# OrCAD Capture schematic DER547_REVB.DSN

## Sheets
1 PAGE2: size C
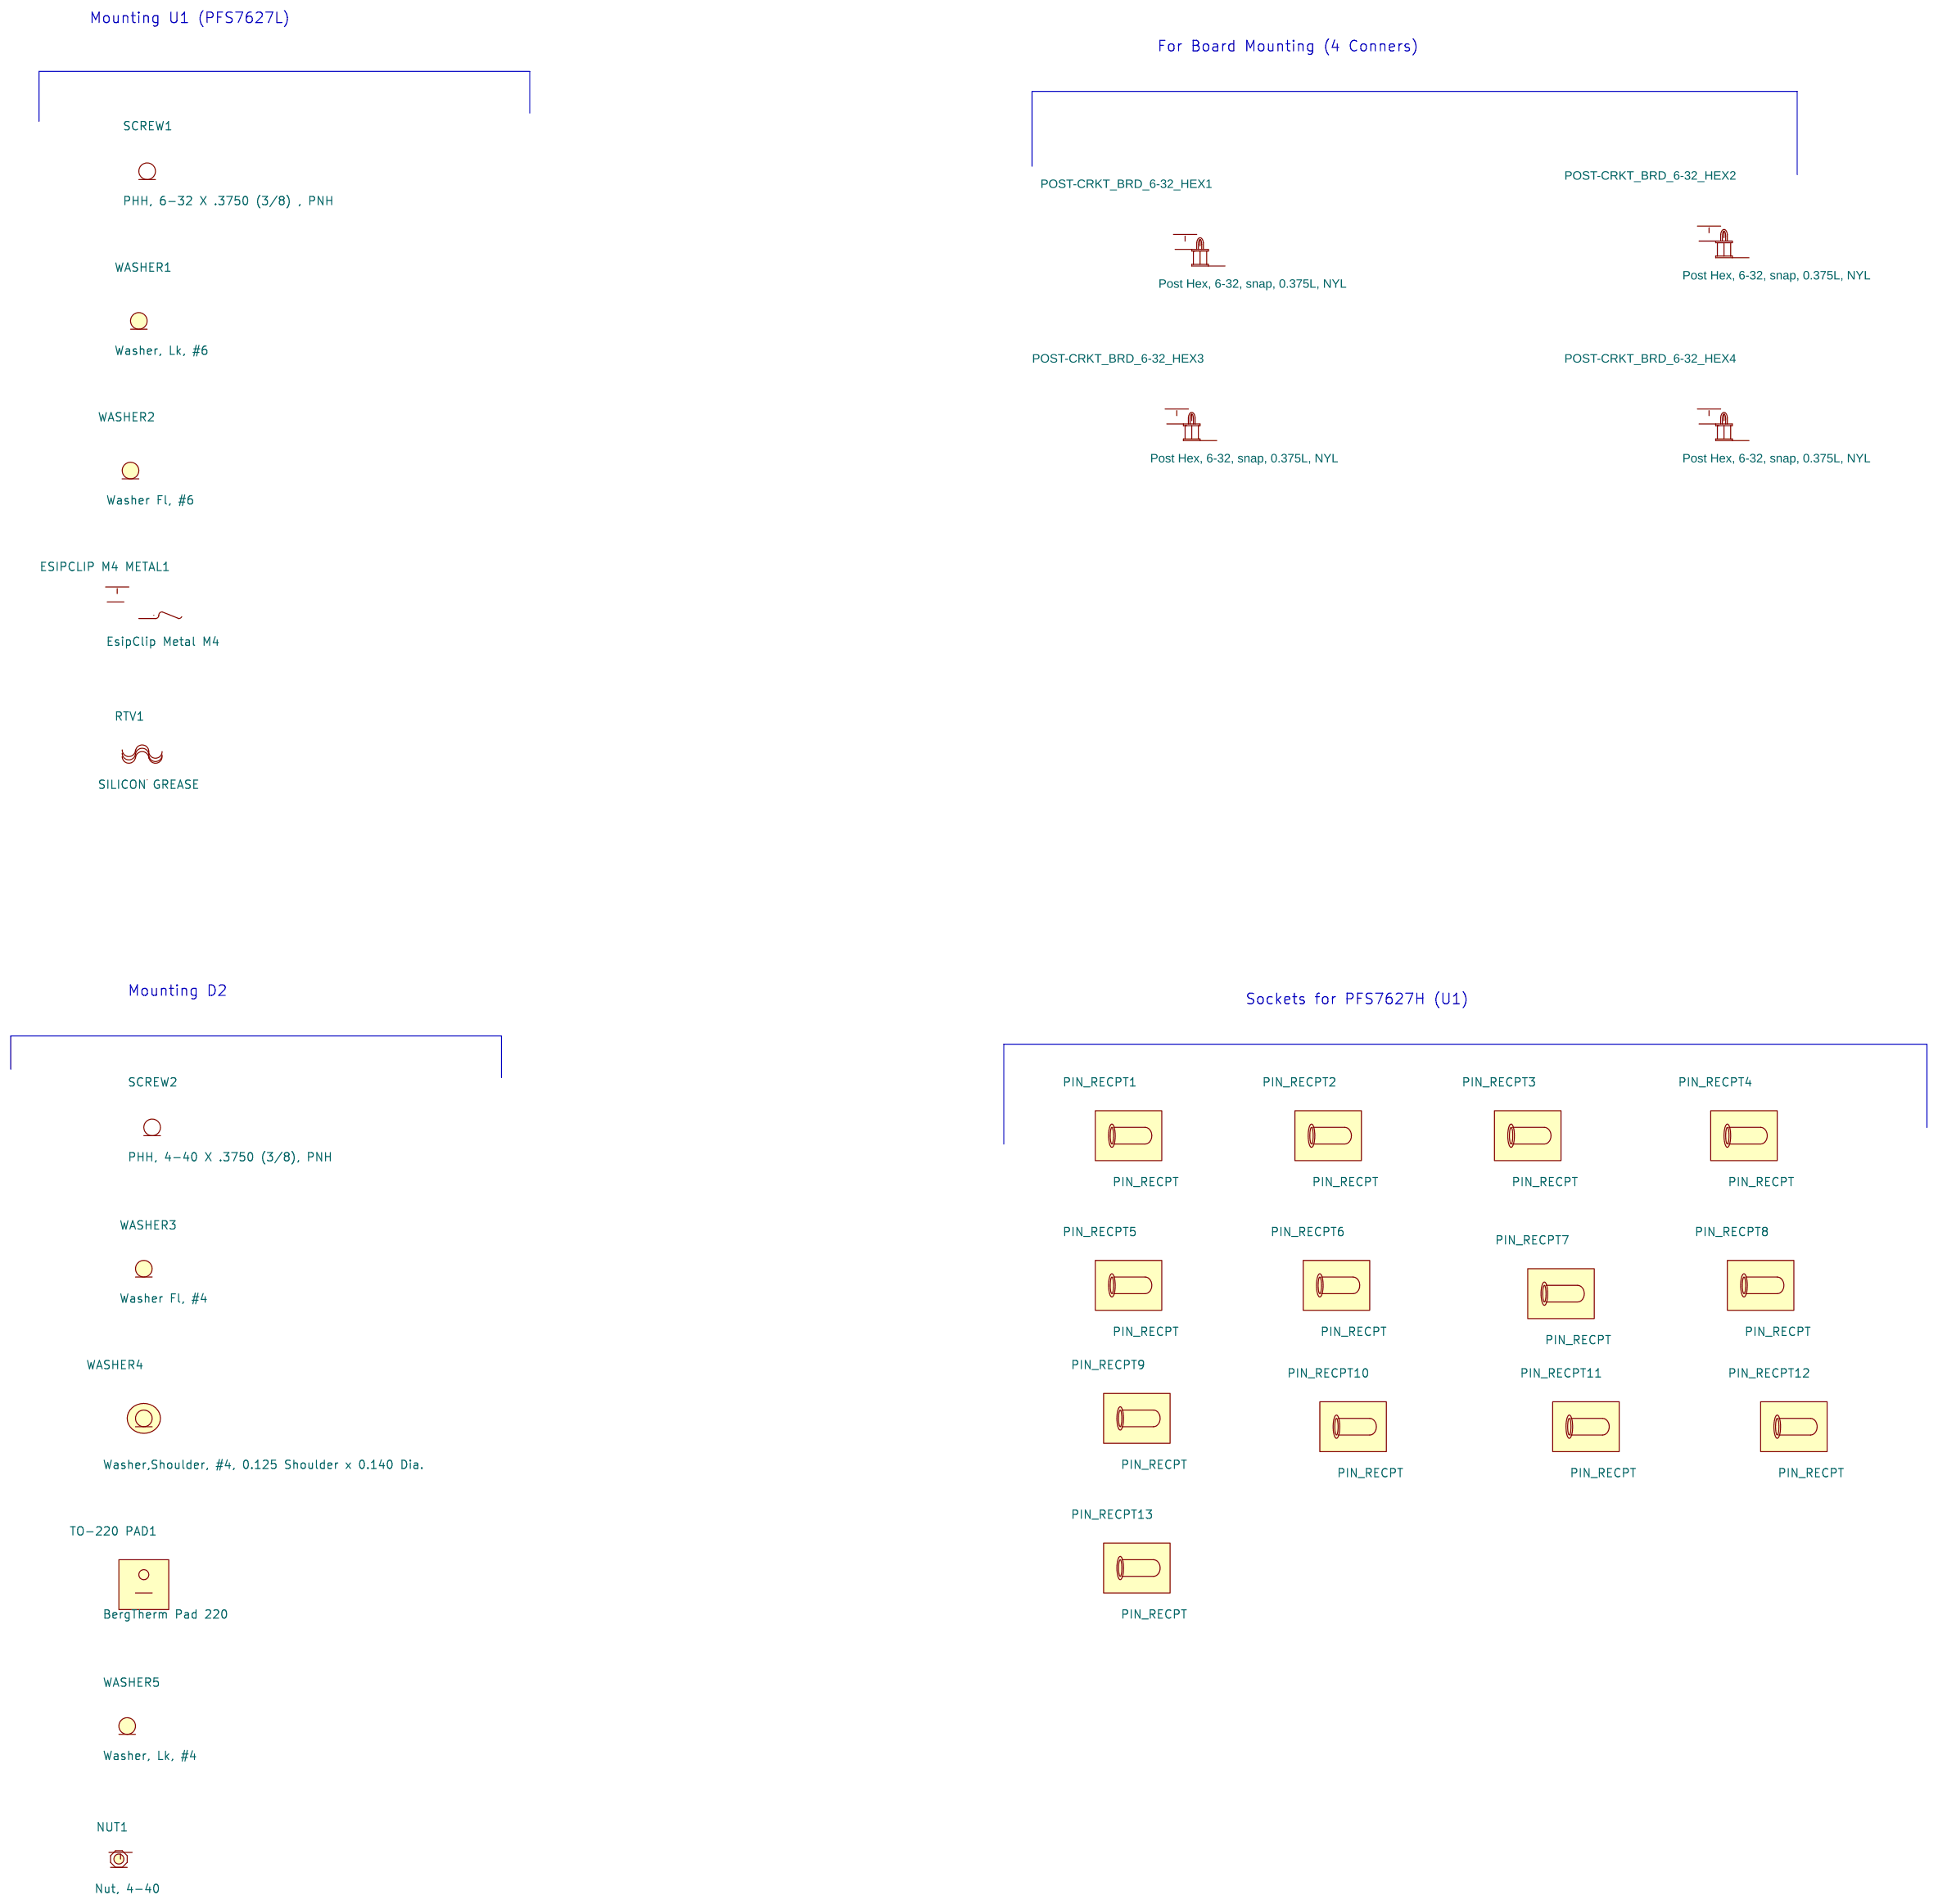
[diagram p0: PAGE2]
2 PAGE1: size C; title: DER547; rev: A
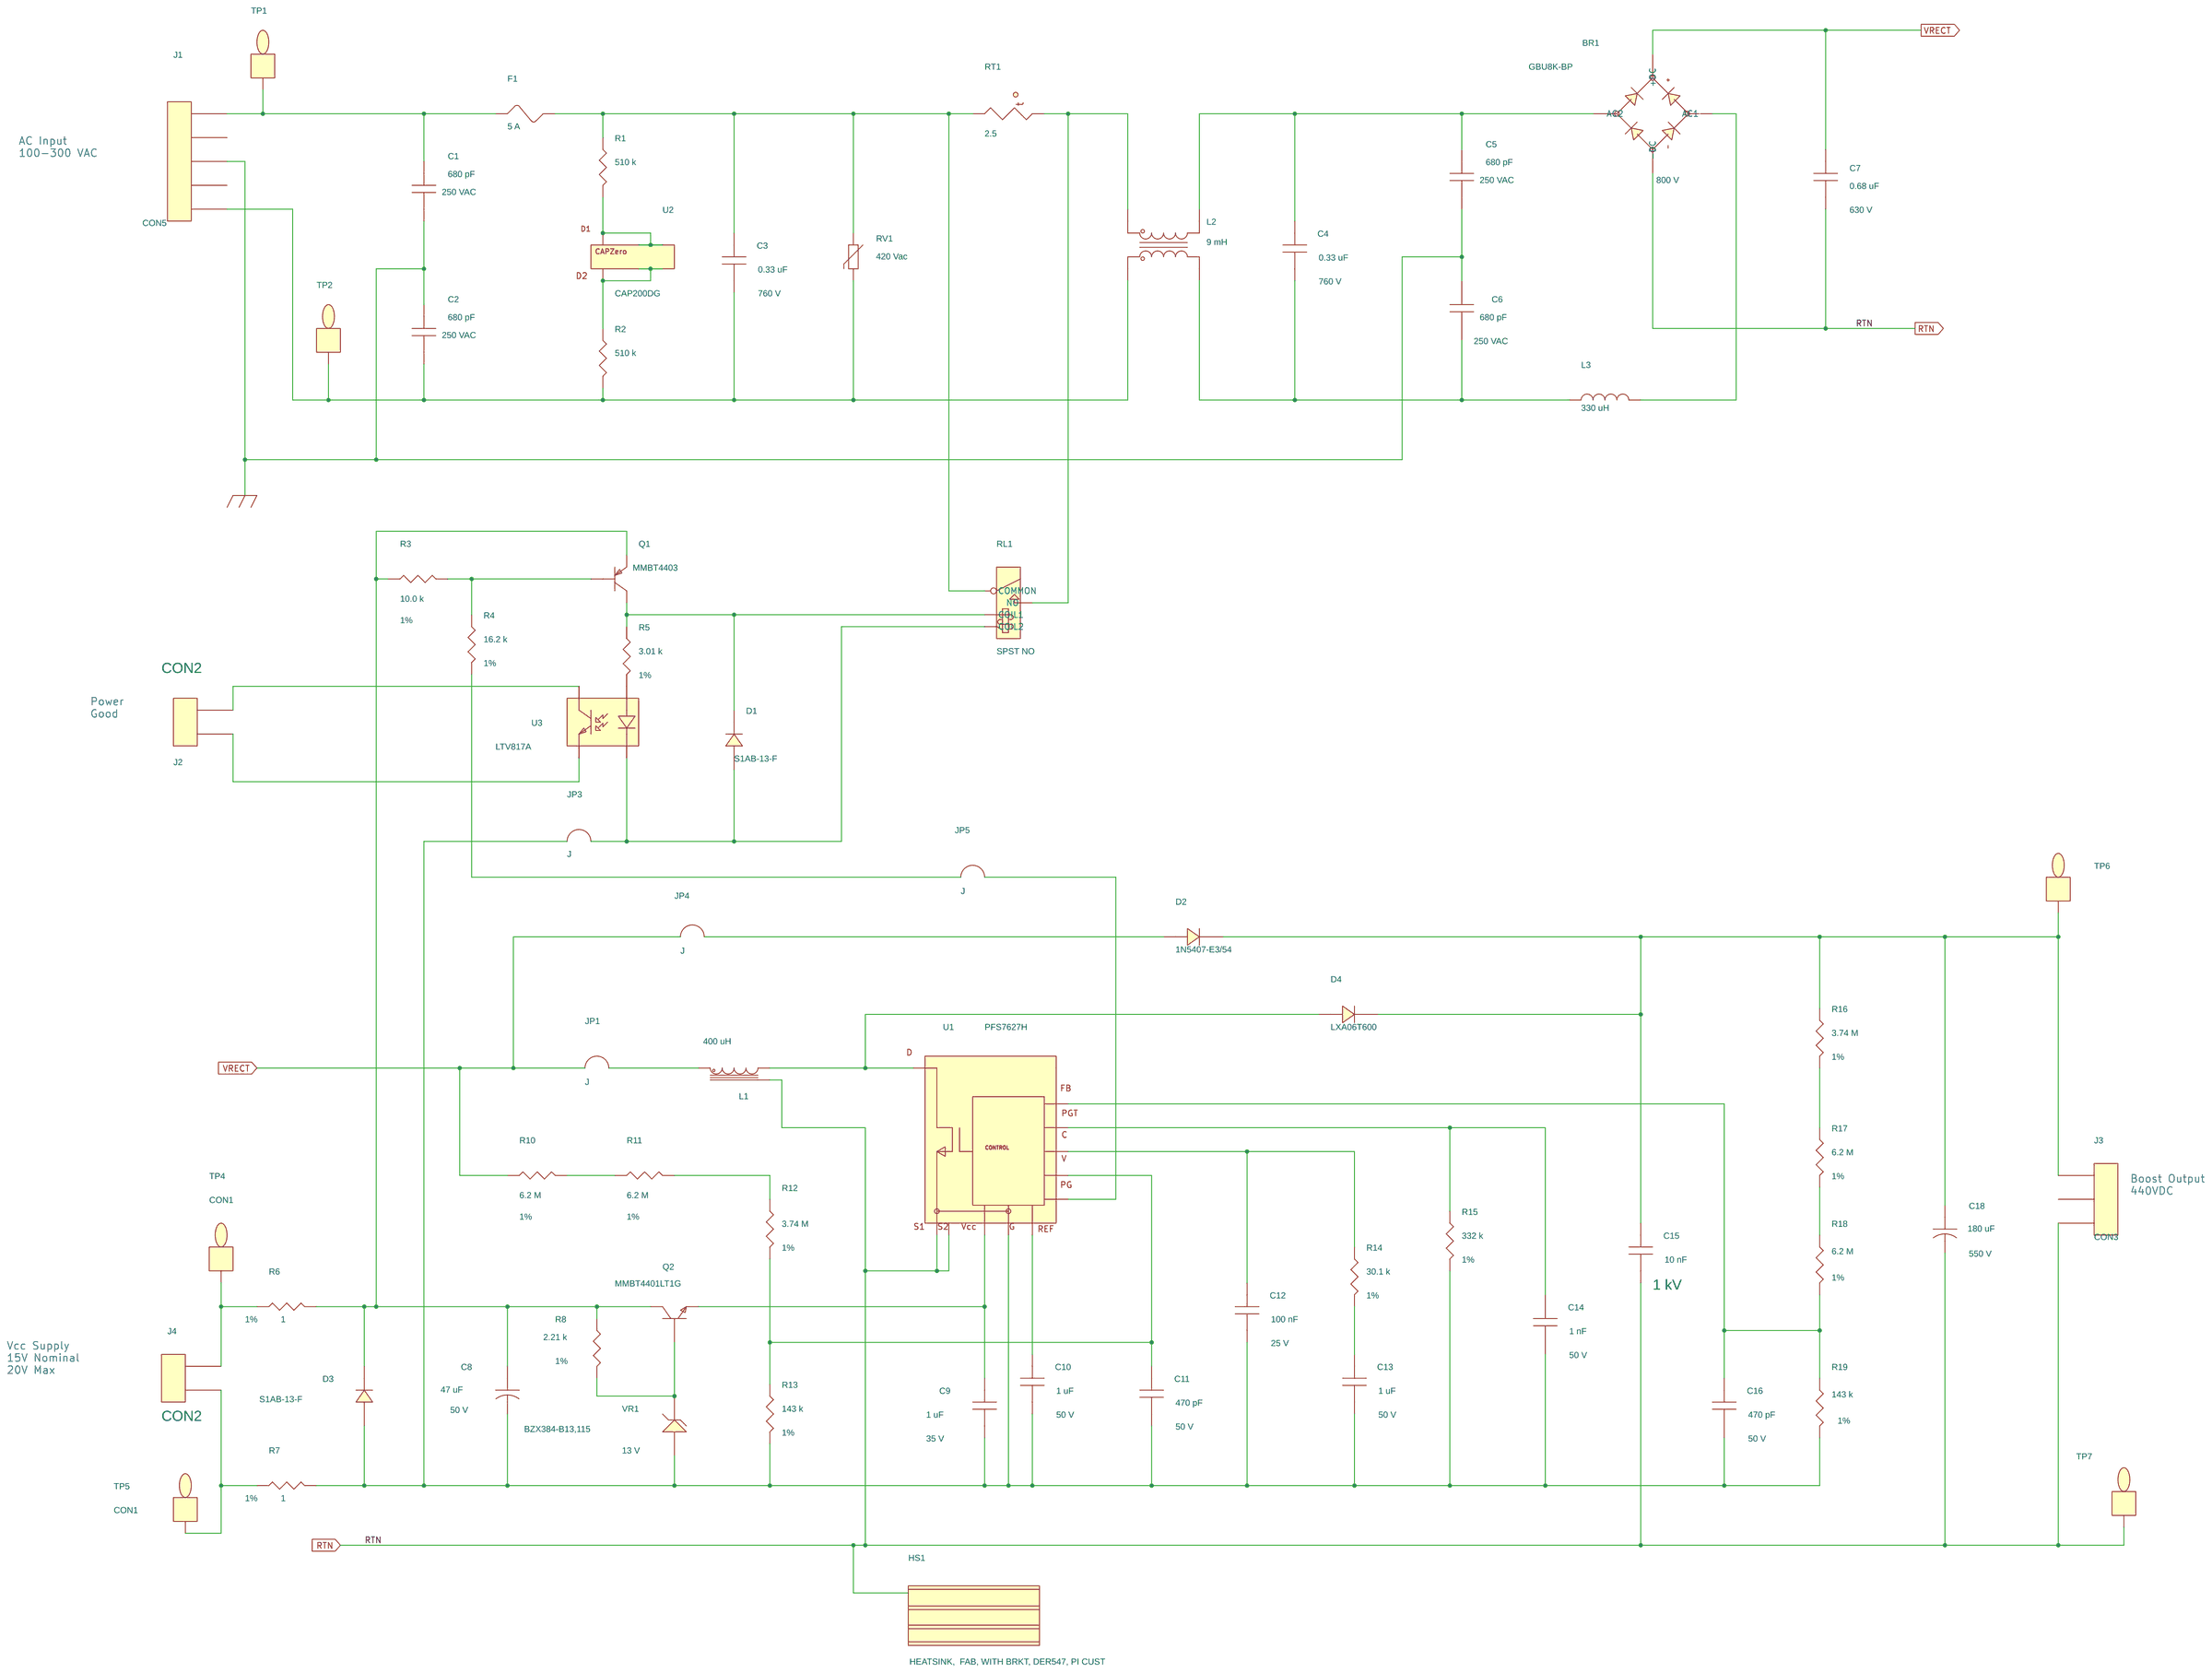
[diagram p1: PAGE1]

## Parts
sheet PAGE1
BR1  GBU8K-BP  [pidaxbridgegbu8]
C1  680 pF  [pinpycaprad470x210ls380040]
C2  680 pF  [pinpycaprad470x210ls380040]
C3  0.33 uF  [pi_np_caprad709x354ls590d050]
C4  0.33 uF  [pi_np_caprad709x354ls590d050]
C5  680 pF  [pinpycaprad470x210ls380040]
C6  680 pF  [pinpycaprad470x210ls380040]
C7  0.68 uF  [pi_np_caprad717x472ls590d050]
C8  47 uF  [pipolcapcyld250ls100030]
C9  1 uF  [pismc0603]
C10  1 uF  [pismc0805]
C11  470 pF  [pismc0805]
C12  100 nF  [pismc0805]
C13  1 uF  [pismc0805]
C14  1 nF  [pismc0805]
C15  10 nF  [pi_np_cap250x200ls170d030]
C16  470 pF  [pismc0805]
C18  180 uF  [pipolcapclyd1377ls394060]
D1  S1AB-13-F  [pismsmb]
D2  1N5407-E3/54  [pidv600x200x060do14]
D3  S1AB-13-F  [pismsmb]
D4  LXA06T600  [pidvt0220acreva]
F1  5 A  [pi_tr5_submin_fuse]
HS1  HEATSINK,  FAB, WITH BRKT, DER547, PI CUST  [PI_HS_DER394_EESIP]
J1  CON5  [pi_hdr_5pin]
J2  CON2  [pi_molex_2pol]
J3  CON3  [pi_hdr_3pin_lock]
J4  CON2  [pi_molex_2pol]
JP1  J  [pi_jumper200]
JP3  J  [pi_jumper200]
JP4  J  [pi_jumper800]
JP5  J  [pi_jumper700]
L1  400 uH  [pi_bobbin_bpq32_20_32-00298-00]
L2  9 mH  [pi_ind_4p_500x1050ls450d46_r1]
L3  330 uH  [pi_toroid_2p_550x950_ls480_d050]
Q1  MMBT4403  [pismsot23132]
Q2  MMBT4401LT1G  [pismsot23132]
R1  510 k  [pismr1206]
R2  510 k  [pismr1206]
R3  10.0 k  [pismr1206]
R4  16.2 k  [pismr1206]
R5  3.01 k  [pismr1206]
R6  1  [pismr1206]
R7  1  [pismr1206]
R8  2.21 k  [pismr0805]
R10  6.2 M  [pismr1206]
R11  6.2 M  [pismr1206]
R12  3.74 M  [pi14wvresd100ls100d030]
R13  143 k  [pismr0805]
R14  30.1 k  [pismr0805]
R15  332 k  [pismr0805]
R16  3.74 M  [pi14wvresd100ls100d030]
R17  6.2 M  [pismr1206]
R18  6.2 M  [pismr1206]
R19  143 k  [pismr0805]
RL1  SPST NO  [pi_rly-omron-g6rl-1a]
RT1  2.5  [pi_rad180x395ls235d031]
RV1  420 Vac  [pidisc500x225ls335x140040]
TP1  CON1  [pitpkeystone125x125]
TP2  CON1  [pitpkeystone125x125]
TP4  CON1  [pitpkeystone125x125]
TP5  CON1  [pitpkeystone125x125]
TP6  CON1  [pitpkeystone125x125]
TP7  CON1  [pitpkeystone125x125]
U1  PFS7627H  [pi_ic_esip16-13_socket_hpii]
U2  CAP200DG  [pi_ic_smd_so8_capzero]
U3  LTV817A  [pi_dip4]
VR1  BZX384-B13,115  [pismsod323]
sheet PAGE2
ESIPCLIP M4 METAL1  EsipClip Metal M4
NUT1  Nut, 4-40
PIN_RECPT1  PIN_RECPT
PIN_RECPT2  PIN_RECPT
PIN_RECPT3  PIN_RECPT
PIN_RECPT4  PIN_RECPT
PIN_RECPT5  PIN_RECPT
PIN_RECPT6  PIN_RECPT
PIN_RECPT7  PIN_RECPT
PIN_RECPT8  PIN_RECPT
PIN_RECPT9  PIN_RECPT
PIN_RECPT10  PIN_RECPT
PIN_RECPT11  PIN_RECPT
PIN_RECPT12  PIN_RECPT
PIN_RECPT13  PIN_RECPT
POST-CRKT_BRD_6-32_HEX1  Post Hex, 6-32, snap, 0.375L, NYL  [pimtgholed156]
POST-CRKT_BRD_6-32_HEX2  Post Hex, 6-32, snap, 0.375L, NYL  [pimtgholed156]
POST-CRKT_BRD_6-32_HEX3  Post Hex, 6-32, snap, 0.375L, NYL  [pimtgholed156]
POST-CRKT_BRD_6-32_HEX4  Post Hex, 6-32, snap, 0.375L, NYL  [pimtgholed156]
RTV1  SILICON GREASE
SCREW1  PHH, 6-32 X .3750 (3/8) , PNH
SCREW2  PHH, 4-40 X .3750 (3/8), PNH
TO-220 PAD1  BergTherm Pad 220
WASHER1  Washer, Lk, #6
WASHER2  Washer Fl, #6
WASHER3  Washer Fl, #4
WASHER4  Washer,Shoulder, #4, 0.125 Shoulder x 0.140 Dia.
WASHER5  Washer, Lk, #4

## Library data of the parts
BR1 = DISCRETE_BRIDGE_+~~-: Disp_Voltage: 800 V; Part Number: 15-00347-00
C1 C2 C5 C6 = CAP_NP: Disp_Voltage: 250 VAC; Part Number: 20-00374-00; Tol: 20; Voltage: 250 VAC
C3 C4 = CAP_NP: Disp_Voltage: 760 V; Part Number: 20-08966-00; Voltage: 760 V
C7 = CAP_NP: Disp_Voltage: 630 V; Part Number: 20-08970-00; Voltage: 630 VDC
C8 = CAP_POL: ALT_SYMBOLS: pipolcapcyld250ls100030h; Disp_Voltage: 50 V; Part Number: 20-00444-00; Tol: 20; Voltage: 50 V
C9 = CAP_NP: Disp_Voltage: 35 V; Part Number: 20-01134-00; Voltage: 35 V
C10 C13 = CAP_NP: Disp_Voltage: 50 V; Part Number: 20-01022-00; Voltage: 50 V
C11 C16 = CAP_NP: Disp_Voltage: 50 V; Part Number: 20-00205-00; Voltage: 50 V
C12 = CAP_NP: Disp_Voltage: 25 V; Part Number: 20-08599-00; Voltage: 25 V
C14 = CAP_NP: Disp_Voltage: 50 V; Part Number: 20-08750-00; Voltage: 50 V
C15 = CAP_NP: Disp_Voltage: 1 kV; Part Number: 20-00894-00; Voltage: 1 kV
C18 = CAP_POL: Disp_Voltage: 550 V; Part Number: 20-08967-00; Voltage: 550 V
D1 D3 = DIODE: Part Number: 15-00994-00
D2 = DIODE: ALT_SYMBOLS: pidax800x225060do15do201ad,pidv300x200x060do14wbead,pidv600x200x060do14; FPLIST: pidv300x200x060do15d0201ad,pidax800x225060do15do201ad,pidv300x200x060do14wbead,pidv600x200x060do14; Part Number: 15-00798-00
D4 = DIODE: Part Number: 15-00853-00
F1 = FUSE: Part Number: 40-00005-00
HS1 = HS-PI_CUSTOM2: Part Number: 61-00211-01
J1 = CON5: Part Number: 35-00242-00
J2 J4 = CON2: Part Number: 35-00137-00
J3 = CON3: Part Number: 35-00243-00
JP1 = JUMPER_1: Part Number: 65-00001-00
JP3 = JUMPER_1: Part Number: 65-00119-00
JP4 = JUMPER_1: Part Number: 65-00047-00
JP5 = JUMPER_1: Part Number: 65-00046-00
L1 = INDUCTOR_DER394_32-00298-00: Part Number: 32-00298-00
L2 = INDUCTOR_4P_revB: FPLIST: pi_ind_4p_500x1050ls450d46,pi_ind_4p_500x1050ls450d46_r1; Part Number: 30-00235-00
L3 = INDUCTOR: Part Number: 32-00295-00
Q1 = PNP_BEC: Part Number: 55-00060-00
Q2 = NPN_BEC: Part Number: 55-00059-00
R1 R2 = R: Part Number: 05-01417-00
R3 = R: Disp_Tol: 1%; Part Number: 05-00289-00
R4 = R: Disp_Tol: 1%; Part Number: 05-00309-00
R5 = R: Disp_Tol: 1%; Part Number: 05-00239-00
R6 R7 = R: Disp_Tol: 1%; Part Number: 05-00481-00
R8 = R: Disp_Tol: 1%; Part Number: 05-03341-00
R10 R11 R17 R18 = R: Disp_Tol: 1%; Part Number: 05-05567-00
R12 R16 = R: ALT_SYMBOLS: pi14wvresd100ls200d030,pi14wresd100ls400d030,pi14wresd100ls500d030; Disp_Tol: 1%; FPLIST: pi14wvresd100ls100d030,pi14wvresd100ls200d030,pi14wresd100ls400d030,pi14wresd100ls500d030; Part Number: 05-05566-00
R13 R19 = R: Disp_Tol: 1%; Part Number: 05-00795-00
R14 = R: Disp_Tol: 1%; Part Number: 05-00730-00
R15 = R: Disp_Tol: 1%; Part Number: 05-00830-00
RL1 = RELAY_SPST_NO_OMRON-G6RL: Part Number: 66-00123-00
RT1 = THERMISTOR: FPLIST: pi_rad180x395ls235d031,pirad550x410ls300040_h; Part Number: 90-00038-00
RV1 = VARISTOR: Part Number: 85-00030-00
TP1 TP5 TP7 = TESTPOINT: Part Number: 35-00042-00
TP2 = TESTPOINT: Part Number: 35-00044-00
TP4 TP6 = TESTPOINT: Part Number: 35-00043-00
U1 = HIPERPFS-4-eSIP-16G: ALT_SYMBOLS: pi_ic_esip16-13_socket_hpii,pi_ic_esip16-13_oval_hpii,pi_ic_eesip_socket; FPLIST: pi_ic_esip16-13_slot_hpii,pi_ic_esip16-13_socket_hpii,pi_ic_esip16-13_oval_hpii,pi_ic_eesip_socket; Part Number: 10-00991-00
U2 = CAPZero: Part Number: 10-00958-00
U3 = OPTO_DIP: Part Number: 53-00008-00
VR1 = DIODE_ZENER: Disp_Voltage: 13 V; Part Number: 15-00819-00
ESIPCLIP M4 METAL1 = EsipClip_Metal_M4: Part Number: 60-00042-00
NUT1 = NUT_HEX_4-40: Part Number: 75-00024-00
PIN_RECPT1-PIN_RECPT13 = PIN_RECPT: Part Number: 66-00050-00
POST-CRKT_BRD_6-32_HEX1-POST-CRKT_BRD_6-32_HEX4 = POST_CRKT_BRD_6-32_HEX: Part Number: 76-00003-00
RTV1 = RTV: Part Number: 66-00084-00
SCREW1 = SCR_6-32: Part Number: 75-00009-00
SCREW2 = SCR_4-40: Part Number: 75-00003-00
TO-220 PAD1 = Berguist_TO-220_Pad: Part Number: 66-00079-00
WASHER1 = WASH_LOCK_6: Part Number: 75-00165-00
WASHER2 = WASH_FLAT_6: Part Number: 75-00033-00
WASHER3 = WASH_FLAT_4: Part Number: 75-00032-00
WASHER4 = WASH_SHLDR_4: Part Number: 75-00154-00
WASHER5 = WASH_LOCK_M6: Part Number: 75-00153-00

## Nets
GND_EARTH: C1.2 C2.1 C5.2 C6.1 J1.3
K: U1.16(K)
NC: U1.14(NC)
RTN: BR1.4(-DC) C7.2 C15.2 C18.2 HS1.2 J3.3 L1.8 TP7.1 U1.10(S1) U1.11(SOURCE)
VRECT: BR1.1(+DC) C7.1 JP1.1 JP4.1 R10.1
N07467: C15.1 C18.1 D2.1 D4.1 J3.1 R16.1 TP6.1
N25080: C8.1 D3.1 Q1.2(EMITTER) Q2.3(COLLECTOR) R3.1 R6.2 R8.1
N182027: C8.2 C9.2 C10.2 C11.2 C12.2 C13.2 C14.2 C16.2 D3.2 JP3.1 R7.2 R13.2 R15.2 R19.1 U1.4(G) VR1.2
N186578: J4.1 R6.1 TP4.1
N737447: J4.2 R7.1 TP5.1
N1260162: C9.1 Q2.2(EMITTER) U1.1(Vcc)
N1260176: JP5.2 U1.8(PG)
N1270725: C2.2 C3.2 J1.5 L2.1 R2.2 RV1.2 TP2.1
N1270759: BR1.3(AC2) C4.1 C5.1 L2.4
N1270767: C4.2 C6.2 L2.2 L3.1
N1270943: BR1.2(AC1) L3.2
N1271019: R1.2 U2.1(NC1) U2.2(D1) U2.3(NC2) U2.4(NC3)
N1271113: C3.1 F1.2 R1.1 RL1.3(COMMON) RT1.1 RV1.1
N1271129: C1.1 F1.1 J1.1 TP1.1
N1844572: D1.2 JP3.2 RL1.2(COIL2) U3.2(C)
N1847765: Q1.1(BASE) R3.2 R4.1
N1847834: JP5.1 R4.2
N1847930: D1.1 Q1.3(COLLECTOR) R5.1 RL1.1(COIL1)
N1948021: J2.1 U3.3(E)
N1951038: J2.2 U3.4(Collector)
N2021552: R2.1 U2.5(NC4) U2.6(NC5) U2.7(D2) U2.8(NC8)
N2052551: L2.3 RL1.4(NO) RT1.2
N2109009: R16.2 R17.1
N2109013: R17.2 R18.2
N2109017: C16.1 R18.1 R19.2 U1.7(FB)
N2110256: C14.1 R15.1 U1.9(PGT)
N2110453: C13.1 R14.2
N2110457: C12.1 R14.1 U1.6(C)
N2110683: C11.1 R12.2 R13.1 U1.5(V)
N2110757: C10.1 U1.3(REF)
N2114150: R10.2 R11.1
N2114158: R11.2 R12.1
N2163226: JP1.2 L1.1
N2199044: Q2.1(BASE) R8.2 VR1.1
N2237206: D4.2 L1.6 U1.13(D)
N2267541: D2.2 JP4.2
N2324039: R5.2 U3.1(A)

Not connected (* = marked no-connect by the designer): HS1 1; J1 2 4; J3 2; POST-CRKT_BRD_6-32_HEX1 1; POST-CRKT_BRD_6-32_HEX2 1; POST-CRKT_BRD_6-32_HEX3 1; POST-CRKT_BRD_6-32_HEX4 1

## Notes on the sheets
sheet 1
- Mounting U1 (PFS7627L)
- For Board Mounting (4 Conners)
- Mounting D2
- Sockets for PFS7627H (U1)
sheet 2
- AC Input
  100-300 VAC
- Power
  Good
- Boost Output
  440VDC
- Vcc Supply
  15V Nominal
  20V Max
